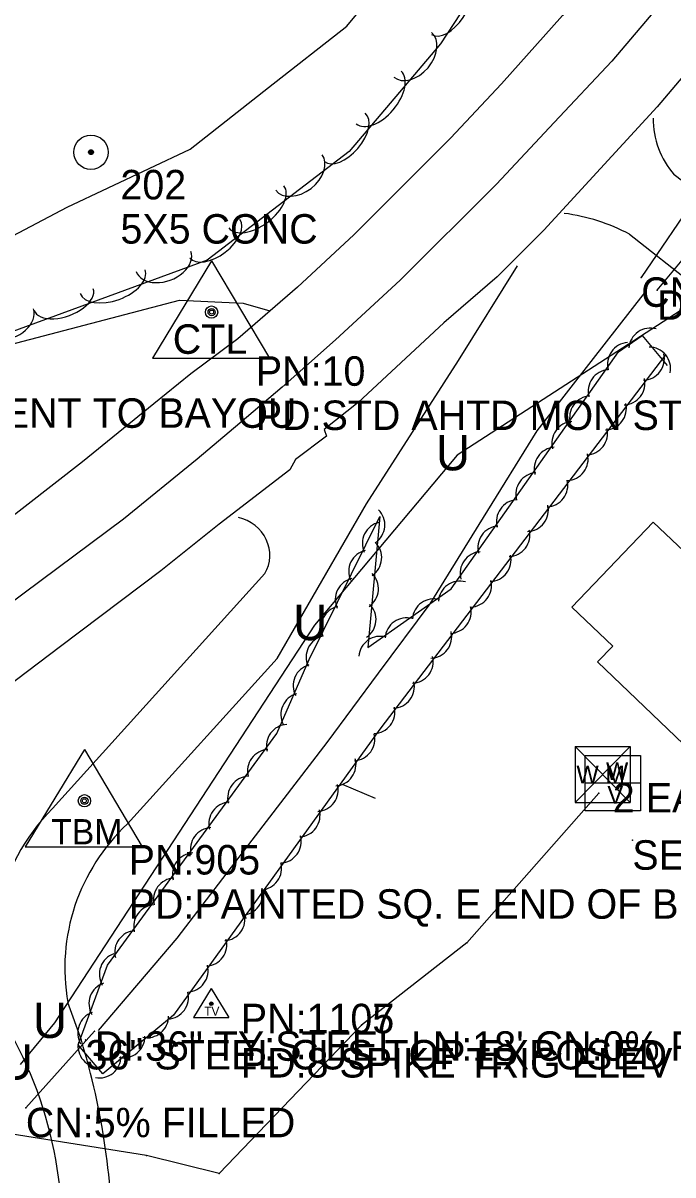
# Model space of a CAD drawing. Extents: x 1451369 to 1458940, y 1868647 to 1875095.
# Drawn here: x 1454638 to 1454748.2, y 1871624.7 to 1871820 of the extents above; entities that cross this region are included whole.
import ezdxf

# ---------------------------------------------------------------- set-up
doc = ezdxf.new("R2010")
doc.units = 0
for name, color, linetype in [('Default', 7, 'Continuous'), ('E_Const Align Station', 7, 'Continuous'), ('E_No Plot', 7, 'Continuous'), ('E_PL and Hook', 7, 'Continuous'), ('E_Property Line', 7, 'Continuous'), ('E_Proposed ROW and Easements', 7, 'Continuous'), ('E_Quarter Section Line', 7, 'Continuous'), ('E_ROW Point Number', 7, 'Continuous'), ('E_Station Offset', 7, 'Continuous'), ('E_Survey Point Number', 7, 'Continuous'), ('E_Tract Number', 7, 'Continuous'), ('R_No Plot', 7, 'Continuous'), ('S_EDGE_PAVEMENT', 7, 'Continuous'), ('S_EXIST_ROW', 7, 'Continuous'), ('S_IRON_PIN_ANNOT', 7, 'Continuous'), ('S_MISC_STRUCTURES_ANNOT', 7, 'Continuous'), ('S_PARKING', 7, 'Continuous'), ('S_PAVEMENT_CROWN', 7, 'Continuous'), ('S_PRIMARY_CTL_ANNOT', 7, 'Continuous'), ('S_SECONDARY_CTL_ANNOT', 7, 'Continuous'), ('S_SIDE_DRAIN_ANNOT', 7, 'Continuous'), ('S_SURVEY_TEXT_ANNOT', 7, 'Continuous'), ('S_TRAILS', 7, 'Continuous'), ('S_WATER_UTILITIES_ANNOT', 7, 'Continuous')]:
    doc.layers.add(name, color=color, linetype=linetype)

msp = doc.modelspace()

# ---------------------------------------------------------------- linework, layer by layer
at = {"layer": 'E_Const Align Station'}
for radius in [2.91, 0.411, 0.262, 0.212, 0.145, 0.0822, 0.0581]:
    msp.add_circle((1454649.53, 1871798.13), radius, dxfattribs=at)
at = {"layer": 'E_No Plot'}
for points in [[(1454735.65, 1871689.45), (1454735.65, 1871689.5), (1454735.65, 1871689.45), (1454735.6, 1871689.45), (1454735.65, 1871689.45), (1454735.65, 1871689.4), (1454735.65, 1871689.45), (1454735.7, 1871689.45)], [(1454713.28, 1871664.05), (1454713.28, 1871664.1), (1454713.28, 1871664.05), (1454713.23, 1871664.05), (1454713.28, 1871664.05), (1454713.28, 1871664), (1454713.28, 1871664.05), (1454713.33, 1871664.05)], [(1454695.42, 1871650.08), (1454695.42, 1871650.13), (1454695.42, 1871650.08), (1454695.37, 1871650.08), (1454695.42, 1871650.08), (1454695.42, 1871650.03), (1454695.42, 1871650.08), (1454695.47, 1871650.08)], [(1454658.95, 1871627.97), (1454658.95, 1871628.02), (1454658.95, 1871627.97), (1454658.9, 1871627.97), (1454658.95, 1871627.97), (1454658.95, 1871627.92), (1454658.95, 1871627.97), (1454659, 1871627.97)], [(1454671.29, 1871624.95), (1454671.29, 1871625), (1454671.29, 1871624.95), (1454671.24, 1871624.95), (1454671.29, 1871624.95), (1454671.29, 1871624.9), (1454671.29, 1871624.95), (1454671.34, 1871624.95)]]:
    msp.add_lwpolyline(points, dxfattribs=at)
at = {"layer": 'E_PL and Hook'}
for p, q in [((1454754.88, 1871794.59), (1454742.84, 1871776.91)), ((1454745.56, 1871774.71), (1454759.22, 1871791.23)), ((1454650.15, 1871649.05), (1454638.48, 1871636.08))]:
    msp.add_line(p, q, dxfattribs=at)
at = {"layer": 'E_Property Line'}
msp.add_lwpolyline([(1454735.46, 1871711.7), (1454767.21, 1871681.32), (1454785.83, 1871700.78), (1454753.4, 1871731.81), (1454751.13, 1871729.43), (1454744.87, 1871735.42), (1454731.07, 1871721), (1454738.01, 1871714.36)], close=True, dxfattribs=at)
at = {"layer": 'E_Proposed ROW and Easements'}
for points in [[(1454741.34, 1871681.45), (1454741.34, 1871681.5), (1454741.34, 1871681.45), (1454741.29, 1871681.45), (1454741.34, 1871681.45), (1454741.34, 1871681.4), (1454741.34, 1871681.45), (1454741.39, 1871681.45)], [(1454648.62, 1871647.58), (1454648.62, 1871647.63), (1454648.62, 1871647.58), (1454648.57, 1871647.58), (1454648.62, 1871647.58), (1454648.62, 1871647.53), (1454648.62, 1871647.58), (1454648.67, 1871647.58)]]:
    msp.add_lwpolyline(points, dxfattribs=at)
at = {"layer": 'E_Quarter Section Line'}
for p, q in [((1454731.65, 1871697.34), (1454740.99, 1871697.34)), ((1454731.65, 1871697.34), (1454731.65, 1871687.85)), ((1454731.65, 1871697.34), (1454740.99, 1871687.85)), ((1454740.99, 1871697.34), (1454731.65, 1871687.85)), ((1454733.32, 1871695.85), (1454742.74, 1871695.85)), ((1454733.32, 1871686.43), (1454733.32, 1871695.85)), ((1454740.99, 1871697.34), (1454740.99, 1871687.85)), ((1454742.74, 1871695.85), (1454742.74, 1871686.43)), ((1454733.32, 1871691.16), (1454742.74, 1871691.16)), ((1454735.65, 1871689.45), (1454713.28, 1871664.05)), ((1454731.65, 1871687.85), (1454740.99, 1871687.85)), ((1454742.74, 1871686.43), (1454733.32, 1871686.43)), ((1454713.28, 1871664.05), (1454695.42, 1871650.08)), ((1454695.42, 1871650.08), (1454671.29, 1871624.95)), ((1454658.95, 1871627.97), (1454595.69, 1871638)), ((1454671.29, 1871624.95), (1454658.95, 1871627.97))]:
    msp.add_line(p, q, dxfattribs=at)
at = {"layer": 'E_ROW Point Number'}
for points in [[(1454738.31, 1871861.57), (1454708.8, 1871816.51), (1454693.32, 1871798.23), (1454669.26, 1871779.8), (1454629.46, 1871765.26), (1454608.9, 1871751.18), (1454586.75, 1871730.8), (1454560.06, 1871707.57), (1454538.95, 1871692.69), (1454521.86, 1871681.88), (1454502.43, 1871685.05), (1454482.33, 1871693.58), (1454468.83, 1871697.08), (1454462.33, 1871676.27), (1454453.21, 1871647.56), (1454439.65, 1871630.76), (1454428.53, 1871638.78), (1454420.08, 1871668), (1454435.67, 1871726.35), (1454455.54, 1871775.31), (1454484.24, 1871834.95)], [(1454746.96, 1871763.75), (1454698.52, 1871700.28), (1454663.53, 1871651.76), (1454651.52, 1871641.81), (1454647.34, 1871646.78), (1454652.32, 1871660.24), (1454681.07, 1871699.56), (1454686.53, 1871712.13), (1454698.5, 1871736.35), (1454696.48, 1871714.12), (1454710.63, 1871724.06), (1454738.99, 1871764.3), (1454743.01, 1871767.05), (1454747.22, 1871761.96)]]:
    msp.add_lwpolyline(points, dxfattribs=at)
for centre, major_axis, ratio, start_param, end_param in [((1454710.23, 1871822.57), (2.93, 4.47), 0.540652, 3.141593, 6.283185), ((1454704.1, 1871814.65), (3.2, 3.78), 0.685259, 3.141593, 6.283185), ((1454698.32, 1871807.42), (3.79, 4.48), 0.550038, 3.141593, 6.283185), ((1454692.59, 1871800.65), (3.45, 4.08), 0.540659, 3.141593, 6.283185), ((1454684.79, 1871794.69), (3.93, 3.01), 0.685276, 3.141593, 6.283185), ((1454677.59, 1871788.86), (4.66, 3.57), 0.550052, 3.141593, 6.283185), ((1454670.55, 1871783.47), (4.24, 3.25), 0.540672, 3.141593, 6.283185), ((1454661.82, 1871779.62), (4.65, 1.7), 0.685298, 3.141594, 6.283187), ((1454653.21, 1871776.2), (5.51, 2.01), 0.550069, 3.141594, 6.283186), ((1454644.89, 1871773.16), (5.02, 1.83), 0.540689, 3.141593, 6.283186), ((1454635.12, 1871769.87), (4.65, 1.7), 0.685298, 3.141594, 6.283187), ((1454744.36, 1871764.68), (-3.1, -1.91), 0.991462, 3.87271, 5.645911), ((1454740.75, 1871762.23), (-2.17, -2.93), 0.990224, 3.850757, 5.623958), ((1454744.19, 1871761.45), (-2.32, 2.81), 0.999261, 3.825789, 5.598989), ((1454743.15, 1871763.1), (2.24, 2.88), 0.990252, 3.835172, 5.608372), ((1454737.47, 1871757.63), (-2.17, -2.93), 0.990224, 3.850757, 5.623958), ((1454739.86, 1871758.91), (2.24, 2.88), 0.990252, 3.835172, 5.608372), ((1454734.33, 1871753.18), (-2.17, -2.93), 0.990224, 3.850757, 5.623958), ((1454736.71, 1871754.66), (2.24, 2.88), 0.990252, 3.835172, 5.608372), ((1454731.31, 1871748.83), (-2.17, -2.93), 0.990224, 3.850757, 5.623958), ((1454733.52, 1871750.43), (2.24, 2.88), 0.990252, 3.835172, 5.608372), ((1454728.32, 1871744.47), (-2.17, -2.93), 0.990224, 3.850757, 5.623958), ((1454730.22, 1871746.1), (2.24, 2.88), 0.990252, 3.835172, 5.608372), ((1454725.19, 1871740.15), (-2.17, -2.93), 0.990224, 3.850757, 5.623958), ((1454726.77, 1871741.63), (2.24, 2.88), 0.990252, 3.835172, 5.608372), ((1454721.91, 1871735.55), (-2.17, -2.93), 0.990224, 3.850757, 5.623958), ((1454695.75, 1871734.88), (2.86, 2.26), 0.9842, 4.645824, 6.419025), ((1454723.47, 1871737.44), (2.24, 2.88), 0.990252, 3.835172, 5.608372), ((1454699.18, 1871731.84), (-2.62, -2.53), 0.989175, 4.174621, 5.947822), ((1454718.77, 1871731.11), (-2.17, -2.93), 0.990224, 3.850757, 5.623958), ((1454720.33, 1871733.19), (2.24, 2.88), 0.990252, 3.835172, 5.608372), ((1454695.21, 1871729.31), (2.86, 2.26), 0.9842, 4.645824, 6.419025), ((1454696.86, 1871727.08), (-2.62, -2.53), 0.989175, 4.174621, 5.947822), ((1454715.75, 1871726.75), (-2.17, -2.93), 0.990224, 3.850757, 5.623958), ((1454717.14, 1871728.95), (2.24, 2.88), 0.990252, 3.835172, 5.608372), ((1454694.59, 1871722.32), (-2.62, -2.53), 0.989175, 4.174621, 5.947822), ((1454694.66, 1871724.05), (2.86, 2.26), 0.9842, 4.645824, 6.419025), ((1454712.07, 1871721.77), (-2.98, -2.1), 0.991398, 3.825789, 5.598989), ((1454713.83, 1871724.63), (2.24, 2.88), 0.990252, 3.835172, 5.608372), ((1454694.25, 1871718.83), (2.86, 2.26), 0.9842, 4.645824, 6.419025), ((1454707.67, 1871718.76), (-2.98, -2.1), 0.991398, 3.825789, 5.598989), ((1454692.16, 1871717.57), (-2.62, -2.53), 0.989175, 4.174621, 5.947822), ((1454703.03, 1871715.54), (-2.98, -2.1), 0.991398, 3.825789, 5.598989), ((1454710.38, 1871720.16), (2.24, 2.88), 0.990252, 3.835172, 5.608372), ((1454689.64, 1871712.53), (-2.62, -2.53), 0.989175, 4.174621, 5.947822), ((1454698.58, 1871712.41), (-2.98, -2.1), 0.991398, 3.825789, 5.598989), ((1454707.09, 1871715.96), (2.24, 2.88), 0.990252, 3.835172, 5.608372), ((1454703.94, 1871711.72), (2.24, 2.88), 0.990252, 3.835172, 5.608372), ((1454687.43, 1871707.68), (-1.45, -3.34), 0.990583, 3.825789, 5.598989), ((1454700.75, 1871707.48), (2.24, 2.88), 0.990252, 3.835172, 5.608372), ((1454685.35, 1871702.8), (-1.45, -3.34), 0.990583, 3.825789, 5.598989), ((1454697.45, 1871703.16), (2.24, 2.88), 0.990252, 3.835172, 5.608372), ((1454682.9, 1871697.47), (-2.15, -2.94), 0.990237, 3.825789, 5.598989), ((1454694.04, 1871698.57), (2.07, 3), 0.99023, 3.804339, 5.57754), ((1454679.69, 1871693.21), (-2.15, -2.94), 0.990237, 3.825789, 5.598989), ((1454690.86, 1871694.29), (2.07, 3), 0.99023, 3.804339, 5.57754), ((1454676.33, 1871688.67), (-2.15, -2.94), 0.990237, 3.825789, 5.598989), ((1454687.83, 1871689.96), (2.07, 3), 0.99023, 3.804339, 5.57754), ((1454673.12, 1871684.28), (-2.15, -2.94), 0.990237, 3.825789, 5.598989), ((1454684.76, 1871685.64), (2.07, 3), 0.99023, 3.804339, 5.57754), ((1454670.02, 1871679.98), (-2.15, -2.94), 0.990237, 3.825789, 5.598989), ((1454681.57, 1871681.22), (2.07, 3), 0.99023, 3.804339, 5.57754), ((1454666.96, 1871675.67), (-2.15, -2.94), 0.990237, 3.825789, 5.598989), ((1454678.24, 1871676.66), (2.07, 3), 0.99023, 3.804339, 5.57754), ((1454663.75, 1871671.41), (-2.15, -2.94), 0.990237, 3.825789, 5.598989), ((1454675.06, 1871672.38), (2.07, 3), 0.99023, 3.804339, 5.57754), ((1454660.39, 1871666.87), (-2.15, -2.94), 0.990237, 3.825789, 5.598989), ((1454672.03, 1871668.05), (2.07, 3), 0.99023, 3.804339, 5.57754), ((1454657.17, 1871662.48), (-2.15, -2.94), 0.990237, 3.825789, 5.598989), ((1454668.96, 1871663.73), (2.07, 3), 0.99023, 3.804339, 5.57754), ((1454654.57, 1871658.75), (-1.99, -3.05), 0.990343, 4.052294, 5.825495), ((1454665.77, 1871659.32), (2.07, 3), 0.99023, 3.804339, 5.57754), ((1454652.81, 1871653.77), (-1.99, -3.05), 0.990343, 4.052294, 5.825495), ((1454662.44, 1871654.76), (2.07, 3), 0.99023, 3.804339, 5.57754), ((1454650.9, 1871648.8), (-1.99, -3.05), 0.990343, 4.052294, 5.825495), ((1454659.08, 1871651.6), (2.18, 2.92), 0.990422, 3.584825, 5.358026), ((1454650.97, 1871646.54), (-0.65, -3.59), 0.998311, 4.70524, 6.47844), ((1454655.06, 1871648.17), (2.18, 2.92), 0.990422, 3.584825, 5.358026), ((1454651, 1871644.77), (2.18, 2.92), 0.990422, 3.584825, 5.358026)]:
    msp.add_ellipse(centre, major_axis=major_axis, ratio=ratio, start_param=start_param, end_param=end_param, dxfattribs=at)
at = {"layer": 'E_Station Offset'}
for p, q in [((1454669.94, 1871656.33), (1454666.93, 1871651.37)), ((1454669.94, 1871656.32), (1454666.93, 1871651.37)), ((1454669.94, 1871656.33), (1454672.89, 1871651.37)), ((1454669.94, 1871656.32), (1454672.89, 1871651.37)), ((1454666.93, 1871651.37), (1454672.89, 1871651.37)), ((1454666.93, 1871651.37), (1454672.89, 1871651.37))]:
    msp.add_line(p, q, dxfattribs=at)
for centre, radius in [((1454669.94, 1871653.72), 0.311), ((1454669.94, 1871653.71), 0.311), ((1454669.94, 1871653.72), 0.183), ((1454669.94, 1871653.71), 0.183), ((1454669.94, 1871653.71), 0.103), ((1454669.94, 1871653.72), 0.103)]:
    msp.add_circle(centre, radius, dxfattribs=at)
at = {"layer": 'E_Survey Point Number'}
for p, q in [((1454752.32, 1871773.08), (1454711.66, 1871746.73)), ((1454711.66, 1871746.73), (1454687.45, 1871717.93)), ((1454687.45, 1871717.93), (1454643.32, 1871650.46)), ((1454643.32, 1871650.46), (1454637.54, 1871643.41))]:
    msp.add_line(p, q, dxfattribs=at)
at = {"layer": 'E_Tract Number'}
for points in [[(1454742.84, 1871776.91), (1454742.84, 1871776.96), (1454742.84, 1871776.91), (1454742.79, 1871776.91), (1454742.84, 1871776.91), (1454742.84, 1871776.86), (1454742.84, 1871776.91), (1454742.89, 1871776.91)], [(1454745.56, 1871774.71), (1454745.56, 1871774.76), (1454745.56, 1871774.71), (1454745.51, 1871774.71), (1454745.56, 1871774.71), (1454745.56, 1871774.66), (1454745.56, 1871774.71), (1454745.61, 1871774.71)], [(1454650.15, 1871649.05), (1454650.15, 1871649.1), (1454650.15, 1871649.05), (1454650.1, 1871649.05), (1454650.15, 1871649.05), (1454650.15, 1871649), (1454650.15, 1871649.05), (1454650.2, 1871649.05)], [(1454638.48, 1871636.08), (1454638.48, 1871636.13), (1454638.48, 1871636.08), (1454638.43, 1871636.08), (1454638.48, 1871636.08), (1454638.48, 1871636.03), (1454638.48, 1871636.08), (1454638.53, 1871636.08)]]:
    msp.add_lwpolyline(points, dxfattribs=at)
at = {"layer": 'R_No Plot'}
for p, q in [((1454669.99, 1871779.72), (1454659.95, 1871763.2)), ((1454669.99, 1871779.72), (1454679.81, 1871763.2)), ((1454659.95, 1871763.2), (1454679.81, 1871763.2)), ((1454648.42, 1871696.84), (1454638.38, 1871680.33)), ((1454648.42, 1871696.84), (1454658.24, 1871680.33)), ((1454638.38, 1871680.33), (1454658.24, 1871680.33))]:
    msp.add_line(p, q, dxfattribs=at)
for centre, radius in [((1454669.99, 1871771.02), 1.04), ((1454669.99, 1871771.02), 0.609), ((1454669.99, 1871771.02), 0.344), ((1454648.42, 1871688.14), 1.04), ((1454648.42, 1871688.14), 0.609), ((1454648.42, 1871688.14), 0.344)]:
    msp.add_circle(centre, radius, dxfattribs=at)
at = {"layer": 'S_EDGE_PAVEMENT'}
for points in [[(1454761.69, 1871860.1), (1454746.95, 1871841.48), (1454738.24, 1871831.39), (1454729.52, 1871821.3), (1454719.14, 1871809.74), (1454710.5, 1871800.49), (1454694.1, 1871784.1), (1454684.53, 1871775.23), (1454674.42, 1871766.5), (1454666.44, 1871760.55), (1454660.2, 1871755.47), (1454648.09, 1871745.64), (1454628.58, 1871730.48), (1454609.07, 1871715.33), (1454598.13, 1871707.6), (1454587.2, 1871699.88), (1454576.26, 1871692.15), (1454565.32, 1871684.43), (1454546.17, 1871671.7), (1454541.43, 1871669), (1454540.33, 1871668.18)], [(1454754.88, 1871816.87), (1454745.54, 1871805.81), (1454735.93, 1871795.36), (1454726.32, 1871784.9), (1454718.41, 1871777.02), (1454709.37, 1871769.22), (1454694.86, 1871755.68), (1454689.05, 1871751.11), (1454689.49, 1871749.99), (1454684.2, 1871746), (1454683.23, 1871744.29), (1454671.26, 1871735.03), (1454661.4, 1871727.14), (1454644.34, 1871714.28), (1454627.27, 1871701.42), (1454623.09, 1871698.14), (1454620.54, 1871697.41), (1454609.79, 1871689.73), (1454599.04, 1871682.04), (1454588.3, 1871674.36), (1454577.55, 1871666.68), (1454567.24, 1871659.01), (1454556.93, 1871651.35), (1454554.66, 1871648.94)]]:
    msp.add_lwpolyline(points, dxfattribs=at)
at = {"layer": 'S_EXIST_ROW'}
for points in [[(1454589.54, 1871755.36), (1454607.61, 1871767.42), (1454623.89, 1871777.43), (1454645.48, 1871788.81), (1454666.35, 1871798.67), (1454679.64, 1871809.1), (1454692.92, 1871819.53), (1454705.5, 1871834.68), (1454700.05, 1871835.66)], [(1454743.54, 1871774.46), (1454734.33, 1871762.66), (1454725.12, 1871750.87), (1454716.05, 1871736.21), (1454706.99, 1871721.55), (1454698.25, 1871709.8), (1454689.52, 1871698.05), (1454676.8, 1871681.45), (1454664.08, 1871664.85), (1454650.76, 1871649.18)], [(1454692.15, 1871690.96), (1454697.73, 1871688.58)]]:
    msp.add_lwpolyline(points, dxfattribs=at)
at = {"layer": 'S_PARKING'}
for points in [[(1454740.86, 1871784.21), (1454751.77, 1871775.62), (1454763.99, 1871757.7), (1454772.51, 1871745.2), (1454764.23, 1871732.24), (1454789.59, 1871712.43), (1454805.28, 1871736.8), (1454781.11, 1871766.25), (1454763.29, 1871783.01), (1454748.44, 1871794.31)], [(1454655.73, 1871684.22), (1454681.13, 1871712.27), (1454696.28, 1871738.5), (1454711.85, 1871762.8), (1454721.84, 1871778.84)], [(1454679.01, 1871726.69), (1454643.02, 1871686.85)], [(1454647.9, 1871647.53), (1454645.6, 1871653.94)]]:
    msp.add_lwpolyline(points, dxfattribs=at)
for centre, major_axis, ratio, start_param, end_param in [((1454758.85, 1871803.82), (1.97, -14.19), 0.97687, 4.570422, 5.304167), ((1454725.37, 1871758.76), (-31.15, -0.9), 0.939446, 4.164987, 4.543126), ((1454673.19, 1871729.98), (-6.39, 2.03), 0.947717, 2.92293, 4.800221), ((1454667.6, 1871662.35), (-4.04, -34.47), 0.999815, 4.045411, 5.192342), ((1454678.57, 1871659.74), (-0.85, -33.47), 0.999995, 3.917955, 4.912134), ((1454575.72, 1871615.11), (-28.7, 62.69), 0.999843, 4.107391, 4.814042), ((1454540.09, 1871612.64), (-9.09, 117), 0.963705, 4.621808, 4.939609)]:
    msp.add_ellipse(centre, major_axis=major_axis, ratio=ratio, start_param=start_param, end_param=end_param, dxfattribs=at)
at = {"layer": 'S_PAVEMENT_CROWN'}
msp.add_lwpolyline([(1454755.56, 1871834.56), (1454746.72, 1871824.06), (1454737.87, 1871813.57), (1454728.08, 1871803.15), (1454718.28, 1871792.74), (1454701.94, 1871776.45), (1454691.02, 1871766.3), (1454681.96, 1871758.27), (1454674.8, 1871752.2), (1454667.54, 1871746.1), (1454655.03, 1871735.92), (1454638.19, 1871723.34), (1454621.35, 1871710.76), (1454615.67, 1871706.77), (1454604.69, 1871698.97), (1454593.71, 1871691.17), (1454582.73, 1871683.38), (1454571.75, 1871675.58), (1454559.5, 1871666.75), (1454547.25, 1871657.93), (1454546.95, 1871657.7)], dxfattribs=at)
at = {"layer": 'S_TRAILS'}
msp.add_lwpolyline([(1454452.76, 1871604.94), (1454453.07, 1871630.27), (1454458.72, 1871654.07), (1454466.48, 1871667.98), (1454475.78, 1871674.76), (1454498.57, 1871690.32), (1454531.15, 1871712.06), (1454574.69, 1871738.84), (1454607.46, 1871754.31), (1454634.61, 1871765.2), (1454664.57, 1871773.03), (1454675.34, 1871772.51), (1454679.89, 1871771.22)], dxfattribs=at)

# ---------------------------------------------------------------- texts
at = {"layer": 'Default'}
for p in [(1454708.03, 1871744.18), (1454683.82, 1871715.39), (1454639.69, 1871647.92), (1454633.91, 1871640.86)]:
    msp.add_text('U', height=6, rotation=360, dxfattribs=at).set_placement(p)
at = {"layer": 'E_Quarter Section Line'}
for s, p in [('W M', (1454731.86, 1871691.11)), ('W', (1454736.87, 1871691.69)), ('V', (1454737.11, 1871687.63))]:
    msp.add_text(s, height=3, rotation=360, dxfattribs=at).set_placement(p)
at = {"layer": 'E_Station Offset'}
msp.add_text('TV', height=1.5, rotation=360, dxfattribs=at).set_placement((1454668.74, 1871651.7))
msp.add_text('TV', height=1.5, rotation=360, dxfattribs=at).set_placement((1454668.74, 1871651.7))
at = {"layer": 'R_No Plot'}
for s, height, p in [('CTL', 5, (1454663.4, 1871763.94)), ('TBM', 4.287, (1454642.77, 1871680.75))]:
    msp.add_text(s, height=height, rotation=360, dxfattribs=at).set_placement(p)
at = {"layer": 'S_IRON_PIN_ANNOT'}
for s, p in [('202', (1454654.53, 1871790.13)), ('5X5 CONC', (1454654.53, 1871782.63))]:
    msp.add_text(s, height=5, dxfattribs=at).set_placement(p)
at = {"layer": 'S_MISC_STRUCTURES_ANNOT'}
msp.add_text('SEPTIC TANK', height=5, dxfattribs=at).set_placement((1454741.34, 1871676.45))
at = {"layer": 'S_PRIMARY_CTL_ANNOT'}
for s, p in [('PN:10', (1454677.49, 1871758.52)), ('PD:STD AHTD MON STAMPED PN:10 11', (1454677.49, 1871751.02)), ('PN:905', (1454655.92, 1871675.64)), ('PD:PAINTED SQ. E END OF BR (BAYOU  11', (1454655.92, 1871668.14))]:
    msp.add_text(s, height=5, dxfattribs=at).set_placement(p)
at = {"layer": 'S_SECONDARY_CTL_ANNOT'}
for s, p in [('PN:1105', (1454674.94, 1871648.71)), ('PN:1107', (1454674.94, 1871648.72)), ('PD:8 SPIKE TRIG ELEV', (1454674.94, 1871641.21)), ('PD:8 SPIKE TRIG ELEV', (1454674.94, 1871641.22))]:
    msp.add_text(s, height=5, dxfattribs=at).set_placement(p)
at = {"layer": 'S_SIDE_DRAIN_ANNOT'}
for s, p in [('CN:50% FILLED', (1454742.84, 1871771.91)), ('DI:36" TY:CMP LN:21\' CN:90% FIL', (1454745.56, 1871769.71)), ('DI:36" TY:STEEL LN:18\' CN:0% FI', (1454650.15, 1871644.05)), ('CN:5% FILLED', (1454638.48, 1871631.08))]:
    msp.add_text(s, height=5, dxfattribs=at).set_placement(p)
at = {"layer": 'S_SURVEY_TEXT_ANNOT'}
for s, p in [('GR RD ENT TO BAYOU', (1454611.18, 1871751.39)), ('36" STEEL CUS TOP EXPOSED', (1454648.62, 1871642.58))]:
    msp.add_text(s, height=5, dxfattribs=at).set_placement(p)
at = {"layer": 'S_WATER_UTILITIES_ANNOT'}
msp.add_text('2 EACH', height=5, dxfattribs=at).set_placement((1454738.03, 1871686.16))

doc.saveas('drawing.dxf')
